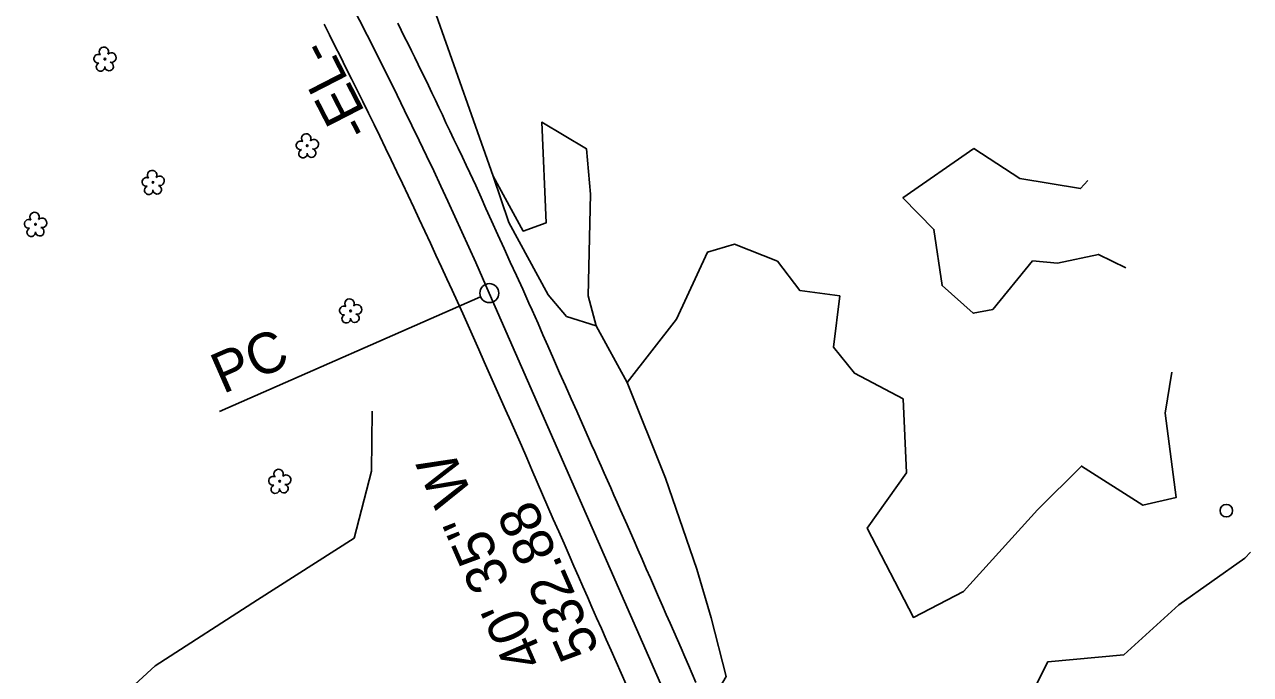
# Model space of a CAD drawing. Extents: x 473158 to 477500, y 500738 to 505114.
# Drawn here: x 475589.3 to 476072.9, y 502009.2 to 502265.8 of the extents above; entities that cross this region are included whole.
import ezdxf

# ---------------------------------------------------------------- set-up
doc = ezdxf.new("R2010")
doc.units = 0
for name, color, linetype in [('Exist Horizontal Alignment', 7, 'Continuous'), ('Exist Horizontal Alignment Direction Label', 7, 'Continuous'), ('Exist Roads EOP', 7, 'Continuous'), ('Exist Utilities Other Pole CELL', 7, 'Continuous'), ('Exist Vegetation Hedge Row', 7, 'Continuous'), ('Exist Vegetation Tree CELL', 7, 'Continuous'), ('Exist Vegetation Woods Line', 7, 'Continuous')]:
    doc.layers.add(name, color=color, linetype=linetype)

msp = doc.modelspace()

# ---------------------------------------------------------------- linework, layer by layer
at = {"layer": 'Exist Horizontal Alignment'}
for p, q in [((475769.2, 502158.21), (475666.19, 502113.05)), ((475968.43, 501713.19), (475772.63, 502159.72))]:
    msp.add_line(p, q, dxfattribs=at)
msp.add_circle((475772.63, 502159.72), 3.75, dxfattribs=at)
msp.add_arc((473989.37, 501377.8), 1947.16, 23.67637, 29.91717, dxfattribs=at)
at = {"layer": 'Exist Roads EOP'}
for points in [[(475826.61, 502005.17), (475824.64, 502009.66), (475822.66, 502014.15), (475820.7, 502018.61), (475818.76, 502023), (475816.84, 502027.3), (475814.96, 502031.53), (475813.11, 502035.69), (475811.3, 502039.81), (475809.53, 502043.87), (475807.8, 502047.88), (475806.03, 502051.98), (475804.15, 502056.31), (475802.15, 502060.85), (475800.04, 502065.62), (475797.88, 502070.49), (475795.75, 502075.37), (475793.63, 502080.23), (475791.54, 502085.09), (475789.45, 502089.93), (475787.37, 502094.74), (475785.28, 502099.52), (475783.19, 502104.26), (475781.11, 502108.99), (475779.01, 502113.71), (475776.92, 502118.44), (475774.83, 502123.16), (475772.73, 502127.9), (475770.62, 502132.65), (475768.5, 502137.42), (475766.37, 502142.21), (475764.25, 502146.98), (475762.13, 502151.68), (475760.03, 502156.31), (475757.94, 502160.87), (475755.84, 502165.43), (475753.71, 502170.04), (475751.56, 502174.7), (475749.38, 502179.41), (475747.19, 502184.15), (475744.99, 502188.87), (475742.79, 502193.58), (475740.58, 502198.28), (475738.37, 502202.97), (475736.14, 502207.65), (475733.9, 502212.33), (475731.65, 502217), (475729.4, 502221.65), (475727.15, 502226.26), (475724.92, 502230.82), (475722.69, 502235.35), (475720.47, 502239.84), (475718.26, 502244.3), (475716.06, 502248.71), (475713.87, 502253.09), (475711.7, 502257.43), (475709.55, 502261.7), (475707.42, 502265.91)], [(475736.48, 502266.28), (475737.85, 502263.56), (475739.21, 502260.85), (475740.56, 502258.15), (475741.91, 502255.45), (475743.25, 502252.75), (475744.59, 502250.03), (475745.93, 502247.27), (475747.28, 502244.48), (475748.63, 502241.65), (475749.99, 502238.8), (475751.36, 502235.91), (475752.73, 502233), (475754.11, 502230.06), (475755.53, 502227.03), (475757.04, 502223.82), (475758.65, 502220.45), (475760.34, 502216.9), (475762, 502213.41), (475763.52, 502210.2), (475764.91, 502207.27), (475767.29, 502202.17), (475769.39, 502197.55), (475771.32, 502193.18), (475773.51, 502188.27), (475775.97, 502182.81), (475778.44, 502177.35), (475780.87, 502172), (475783.32, 502166.65), (475785.79, 502161.27), (475787.04, 502158.54), (475788.28, 502155.78), (475789.54, 502152.99), (475791.86, 502147.77), (475793.79, 502143.33), (475795.69, 502138.91), (475797.94, 502133.74), (475800.34, 502128.29), (475802.68, 502123.07), (475804.95, 502118.02), (475807.14, 502113.09), (475809.37, 502108.04), (475811.75, 502102.63), (475812.99, 502099.84), (475814.23, 502097.04), (475815.47, 502094.25), (475816.72, 502091.46), (475817.98, 502088.65), (475819.25, 502085.79), (475820.52, 502082.9), (475821.81, 502079.97), (475823.11, 502077.02), (475824.4, 502074.08), (475825.69, 502071.15), (475826.98, 502068.22), (475828.31, 502065.19), (475829.74, 502061.93), (475831.26, 502058.45), (475832.88, 502054.74), (475834.53, 502050.94), (475836.16, 502047.2), (475837.77, 502043.51), (475839.36, 502039.87), (475840.92, 502036.3), (475842.45, 502032.82), (475843.93, 502029.43), (475845.39, 502026.13), (475846.83, 502022.86), (475848.27, 502019.55), (475849.72, 502016.2), (475851.18, 502012.82), (475852.65, 502009.42), (475854.11, 502006.04)]]:
    msp.add_lwpolyline(points, dxfattribs=at)
at = {"layer": 'Exist Utilities Other Pole CELL'}
msp.add_circle((476063.38, 502073.85), 2.46, dxfattribs=at)
at = {"layer": 'Exist Vegetation Hedge Row'}
for points in [[(475814.74, 502146.78), (475803.14, 502150.57), (475795.81, 502159.12), (475780.36, 502187.68), (475774.11, 502205.93)], [(475894.26, 501934.48), (475889.57, 501940.81), (475879.11, 501961.95), (475862.96, 502002.92), (475866.06, 502008.33), (475860.15, 502031.52), (475854.46, 502050.74), (475842.16, 502086.69), (475826.98, 502124.47)]]:
    msp.add_lwpolyline(points, dxfattribs=at)
at = {"layer": 'Exist Vegetation Tree CELL'}
for p, q in [((475620.95, 502252.13), (475620.95, 502252.13)), ((475700.8, 502217.92), (475700.8, 502217.92)), ((475639.97, 502203.46), (475639.97, 502203.46)), ((475593.59, 502186.9), (475593.59, 502186.9)), ((475717.89, 502152.73), (475717.89, 502152.73)), ((475689.89, 502085.47), (475689.89, 502085.47))]:
    msp.add_line(p, q, dxfattribs=at)
for centre in [(475620.95, 502252.13), (475700.8, 502217.92), (475639.97, 502203.46), (475593.59, 502186.9), (475717.89, 502152.73), (475689.89, 502085.47)]:
    msp.add_circle(centre, 0.326, dxfattribs=at)
for centre, radius, start, end in [((475618.35, 502252.28), 1.73, 62.6636, 279.3457), ((475620.57, 502255), 1.86, 330.1651, 219.7134), ((475623.5, 502252.72), 1.9, 257.1011, 134.1999), ((475619.25, 502249.01), 1.69, 111.5671, 6.231), ((475622.63, 502249.23), 1.7, 181.2822, 74.56), ((475700.42, 502220.8), 1.86, 330.1651, 219.7134), ((475703.35, 502218.51), 1.9, 257.1011, 134.1999), ((475698.2, 502218.08), 1.73, 62.6636, 279.3457), ((475699.1, 502214.8), 1.69, 111.5671, 6.231), ((475702.47, 502215.02), 1.7, 181.2822, 74.56), ((475639.58, 502206.33), 1.86, 330.1651, 219.7134), ((475642.52, 502204.05), 1.9, 257.1011, 134.1999), ((475637.36, 502203.61), 1.73, 62.6636, 279.3457), ((475638.26, 502200.34), 1.69, 111.5671, 6.231), ((475641.64, 502200.56), 1.7, 181.2822, 74.56), ((475593.21, 502189.78), 1.86, 330.1651, 219.7134), ((475590.99, 502187.06), 1.73, 62.6636, 279.3457), ((475596.14, 502187.49), 1.9, 257.1011, 134.1999), ((475591.89, 502183.78), 1.69, 111.5671, 6.231), ((475595.27, 502184), 1.7, 181.2822, 74.56), ((475717.5, 502155.61), 1.86, 330.1651, 219.7134), ((475715.28, 502152.89), 1.73, 62.6636, 279.3457), ((475720.43, 502153.32), 1.9, 257.1011, 134.1999), ((475716.18, 502149.61), 1.69, 111.5671, 6.231), ((475719.56, 502149.83), 1.7, 181.2822, 74.56), ((475689.51, 502088.34), 1.86, 330.1651, 219.7134), ((475687.29, 502085.62), 1.73, 62.6636, 279.3457), ((475692.44, 502086.06), 1.9, 257.1011, 134.1999), ((475688.19, 502082.35), 1.69, 111.5671, 6.231), ((475691.57, 502082.57), 1.7, 181.2822, 74.56)]:
    msp.add_arc(centre, radius, start, end, dxfattribs=at)
at = {"layer": 'Exist Vegetation Woods Line'}
for points in [[(475886.38, 502172.36), (475869.39, 502179.12), (475858.65, 502175.9), (475846.51, 502149.47), (475826.98, 502124.47), (475814.74, 502146.78), (475811.61, 502158.67), (475812.53, 502198.84), (475810.93, 502216.74), (475793.33, 502227.19), (475795.06, 502187.54), (475786, 502184.24), (475774.11, 502205.93), (475751.7, 502269.54), (475722.89, 502333.61), (475798.79, 502380.12), (475809.6, 502387.08), (475884.97, 502384.38), (475923.94, 502390.38)], [(476023.8, 502169.76), (476012.92, 502175.04), (475996.78, 502171.54), (475986.97, 502172.52), (475971.22, 502153.21), (475963.54, 502151.82), (475951.23, 502162.73), (475948.05, 502184.89), (475935.82, 502197.31), (475963.73, 502216.8)], [(476008.74, 502204.17), (476005.89, 502201.01), (475981.91, 502204.99), (475963.73, 502216.8)], [(476041.83, 502128.52), (476039.25, 502112.31), (476043.61, 502079.09), (476030.5, 502075.96), (476006.25, 502091.43), (475988.91, 502074.11), (475959.75, 502041.98), (475939.91, 502031.69), (475921.74, 502066.94), (475937.25, 502088.75), (475935.86, 502117.97), (475916.68, 502128.12), (475908.37, 502138.44), (475910.86, 502158.61), (475895.07, 502160.77), (475886.38, 502172.36)], [(475640.81, 502012.54), (475681.16, 502038.68), (475719.36, 502062.99), (475726.12, 502089.42), (475726.4, 502113.08)], [(475984.22, 501729.43), (475952.41, 501810.41), (475938.29, 501838.59), (475925.48, 501856.19), (475904.69, 501908.62), (475894.26, 501934.48), (475891.89, 501946.09), (475913.49, 501955.7), (475961.43, 501988.61), (475984.27, 501997.05), (475993.03, 502014.2), (476022.92, 502016.87), (476044.62, 502036.72), (476070.75, 502055.07), (476072.92, 502057.47)], [(475793.12, 501950.48), (475783.69, 501942.76), (475766.82, 501922.52), (475747.14, 501911.49), (475680.82, 501882.36), (475661.56, 501905.49), (475634.68, 501944.13), (475619.87, 501993.37), (475640.81, 502012.54)]]:
    msp.add_lwpolyline(points, dxfattribs=at)

# ---------------------------------------------------------------- texts
at = {"layer": 'Exist Horizontal Alignment'}
msp.add_text('PC', height=16, rotation=23.6764, dxfattribs=at).set_placement((475667.55, 502119.79))
at = {"layer": 'Exist Horizontal Alignment Direction Label'}
for s, rotation, p in [('-EL-', 117.1861, (475727.01, 502224.89)), ('N 23%%d 40\' 35" W', 113.6764, (475818.7, 501960.17)), ('532.88', 113.6764, (475816.28, 502019))]:
    msp.add_text(s, height=16, rotation=rotation, dxfattribs=at).set_placement(p)

doc.saveas('drawing.dxf')
